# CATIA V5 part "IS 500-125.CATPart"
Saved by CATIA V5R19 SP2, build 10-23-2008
Part number: IS 500-125
Bounding box of the stored display mesh (mm): x -22.494 to 22.494, y -22.494 to 22.494, z 0 to 335
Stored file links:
  C:\Users\Bora\Desktop\3D Katı model\IS serisi\IS 500\IS 500-125.CATPart
  C:\Program Files\Dassault Systemes\B19\intel_a\reffiles\standard\MetricThickPitch.txt
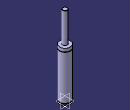
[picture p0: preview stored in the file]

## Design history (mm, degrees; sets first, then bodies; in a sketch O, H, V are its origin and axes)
Body1 (main body)
  Sketch1 on yz-plane, origin (0, 0, 0), H (0, 1, 0), V (0, 0, 1)
    point P3 (10, 334)
    point P5 (10, 334)
    point P7 (22.5, 194.5)
    point P8 (22.5, 192.5)
    point P12 (22.5, 192.5)
    point P13 (22.5, 194.5)
    line L1 (22.5, 0) -> (22.5, 4)
    line L2 (10, 334) -> (10, 208)
    arc A1 centre (9, 334) radius 1 from (10, 334) to (9, 335) ccw
    arc A2 centre (22.5, 193.5) radius 1 from (22.5, 194.5) to (22.5, 192.5) ccw
    line L3 (20, 7.5) -> (20, 4)
    line L4 (22.5, 7.5) -> (22.5, 192.5)
    line L5 (22.5, 194.5) -> (22.5, 208)
    line L6 (9, 335) -> (0, 335)
    point P15 (0, 335)
    line L7 (10, 208) -> (22.5, 208)
    line L8 (20, 7.5) -> (22.5, 7.5)
    line L9 (20, 4) -> (22.5, 4)
    line L10 (0, 0) -> (22.5, 0)
    coincidence: P15 V, P3 P5, P7 P13, P8 P12
    tangency: L6 A1
    horizontal: L7 H, L8 H, L9 H, L10 H
  Shaft1: profile Sketch1, axis Sketch1.V, angle 360
  Sketch2 on face of Shaft1 from Sketch1.L10, origin (0, 0, 0), H (1, 0, 0), V (0, -1, 0)
    point P1 (10, 0)
    distance P1 V = 10
  Hole1: placed by Sketch2, at (10, 0, 0) direction (0, 0, 1), diameter 6.647, depth 13, threaded "M8", thread diameter 8, thread depth 13, pitch 1.25
  Sketch3 on face of Shaft1 from Sketch1.L10, origin (0, 0, 0), H (1, 0, 0), V (0, -1, 0)
    point P1 (-10, 0)
    distance P1 V = 10
  Hole2: placed by Sketch3, at (-10, 0, 0) direction (0, 0, 1), diameter 6.647, depth 13, threaded "M8", thread diameter 8, thread depth 13, pitch 1.25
